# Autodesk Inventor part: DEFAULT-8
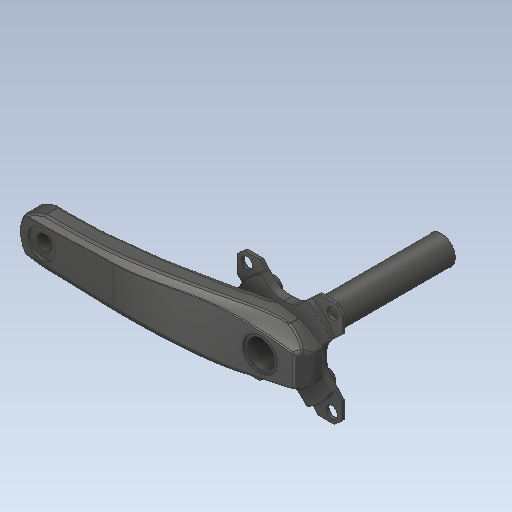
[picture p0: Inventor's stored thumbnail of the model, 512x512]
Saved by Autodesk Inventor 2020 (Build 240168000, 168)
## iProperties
Created: 2015-11
Part Number: DEFAULT-8
Material: solidworks materials|6061-T6 (SS)|164
Document SubType Name: Modeling
Designer: Tomasz
Density: 2.7 g/cm^3
Appearance: 73,73,73
Sending System: SolidWorks 2017
Last Author: Tomasz
Last Saved: 2017-10-01
Author: Tomasz
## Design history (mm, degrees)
feature "Imported1"
node "Bryła1"
